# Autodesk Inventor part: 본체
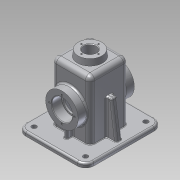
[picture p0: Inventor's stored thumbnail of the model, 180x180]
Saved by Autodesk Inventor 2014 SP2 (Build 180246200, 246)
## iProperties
Created: 2016-08
Part Number: 본체
Material: 알루미늄 6061
Document SubType Name: Modeling
Designer: user
Density: 2.71 g/cm^3
Appearance: 알루미늄 - 평지
Mass: 799.652 g
Surface Area: 913.3 cm^2
Volume: 295.075 cm^3
Author: user
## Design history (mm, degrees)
sketch "스케치2"
  geometry: L1 (52.5, -60)-(-52.5, -60); L2 (-52.5, -60)-(-52.5, 60); L3 (-52.5, 60)-(52.5, 60); L4 (52.5, 60)-(52.5, -60); L5 (52.5, -60)-(-52.5, 60); L6 (-52.5, -60)-(52.5, 60); 1 further point
  constraints: 12 end point, 2 midpoint, 2 parallel, 1 horizontal, 1 perpendicular
  dimensions: "d0" = 105 distance of L2.end L3.end; "d1" = 120 distance of L1.end L2.end
extrude "돌출1" new body sketch "스케치2" distance "d2" = 3; taper "d3" = 0 deg
sketch "스케치3"
  geometry: L1 (57.5, -65)-(-57.5, -65); L2 (-57.5, -65)-(-57.5, 65); L3 (-57.5, 65)-(57.5, 65); L4 (57.5, 65)-(57.5, -65); L5 (57.5, -65)-(-57.5, 65); L6 (-57.5, -65)-(57.5, 65); 1 further point
  constraints: 12 end point, 2 midpoint, 2 parallel, 1 horizontal, 1 perpendicular
  dimensions: "d4" = 115 distance of L2.end L3.end; "d5" = 130 distance of L1.end L2.end
extrude "돌출2" join sketch "스케치3" distance "d6" = 7; taper "d7" = 0 deg
sketch "스케치4"
  geometry: L1 (-32.5, -32.5)-(32.5, -32.5); L2 (32.5, -32.5)-(32.5, 32.5); L3 (32.5, 32.5)-(-32.5, 32.5); L4 (-32.5, 32.5)-(-32.5, -32.5); L5 (-32.5, -32.5)-(32.5, 32.5); L6 (32.5, -32.5)-(-32.5, 32.5); 1 further point
  constraints: 12 end point, 2 midpoint, 2 parallel, 1 horizontal, 1 perpendicular
  dimensions: "d8" = 65 distance of L3.end L2.end; "d9" = 65 distance of L2.end L1.end
extrude "돌출3" join sketch "스케치4" distance "d10" = 100; taper "d11" = 0 deg
sketch "스케치5"
  geometry: L1 (32.5, -32.5)-(-32.5, -32.5) reference; L2 (-32.5, -32.5)-(-32.5, 32.5) reference; L3 (-32.5, 32.5)-(32.5, 32.5) reference; L4 (32.5, 32.5)-(32.5, -32.5) reference; L5 (27.5, 27.5)-(-27.5, 27.5); L6 (-27.5, 27.5)-(-27.5, -27.5); L7 (-27.5, -27.5)-(27.5, -27.5); L8 (27.5, -27.5)-(27.5, 27.5); 1 further point
  constraints: 8 end point, 3 other
  dimensions: "d12" = 5 distance between parallel lines of L3 L5
extrude "돌출4" cut sketch "스케치5" distance "d13" = 105; taper "d14" = 0 deg
sketch "스케치6"
  geometry: C1 r 27.5 at (32.5, 45); 1 further point
  constraints: 1 centre point, 1 vertical alignment
  dimensions: "d15" = 55 diameter of C1; "d16" = 55 distance of point (32.5, -10) C1.centre
extrude "돌출5" join sketch "스케치6" distance "d17" = 15; taper "d18" = 0 deg
fillet "모깎기1" dims "d19" = 8
fillet "모깎기2" dims "d20" = 8
fillet "모깎기3" dims "d21" = 3
sketch "스케치9"
  geometry: L1 (-57.5, -65)-(-57.5, 65) reference; L2 (-32.5, 24.5)-(-32.5, -24.5) reference; L3 (-49.5, 5)-(-49.5, -5); L4 (-49.5, -5)-(-32.5, -5); L5 (-49.5, 5)-(-32.5, 5); L6 (-32.5, 5)-(-32.5, -5); 2 further points
  constraints: 8 end point, 2 perpendicular, 2 point on line, 1 collinear, 1 horizontal alignment, 1 midpoint, 1 parallel
  dimensions: "d36" = 10 distance of L3.start L3.end; "d37" = 8 distance between parallel lines of L1 L3
extrude "돌출7" join sketch "스케치9" distance "d38" = 60; taper "d39" = 0 deg
feature "면 기울기1" dims angle "d40" = 8 deg
sketch "스케치10"
  geometry: L1 (24.5, -32.5)-(-24.5, -32.5) reference; L2 (-3, -42.5)-(3, -42.5); L3 (-24.5, -27.5)-(24.5, -27.5) reference; L4 (3, -42.5)-(3, -27.5); L5 (-3, -42.5)-(-3, -27.5); L6 (-3, -27.5)-(3, -27.5); 2 further points
  constraints: 8 end point, 2 perpendicular, 2 point on line, 1 collinear, 1 midpoint, 1 parallel, 1 vertical alignment
  dimensions: "d41" = 15 distance of L2.end L4.end; "d42" = 6 distance of L2.start L2.end
extrude "돌출8" join sketch "스케치10" stored distance "d43" = 70; taper "d44" = 0 deg
sketch "스케치11"
  geometry: L1 (32.5, -47)-(32.5, 45) reference; 2 further points
  constraints: 1 other
  dimensions: "d46" = 32.5 distance from line of L1 point (0, -39); "d189" = 94 distance of point (0, 55) point (0, -39)
hole "구멍1" diameter "d51" = 35; stored, may be unused: countersink angle "d55" = 90 deg, drill point angle "d57" = 0 deg; dims "d49" = 10, "d50" = 10, "d52" = 6, "d53" = 4, "d54" = 2, "d56" = 17
hole "구멍2" diameter "d60" = 35; stored, may be unused: countersink angle "d64" = 90 deg, drill point angle "d66" = 0 deg; dims "d58" = 10, "d59" = 10, "d61" = 6, "d62" = 4, "d63" = 2, "d65" = 17
hole "구멍3" diameter "d69" = 30; stored, may be unused: countersink angle "d73" = 90 deg, drill point angle "d75" = 0 deg; dims "d67" = 10, "d68" = 10, "d70" = 6, "d71" = 4, "d72" = 2, "d74" = 3
hole "구멍4" diameter "d78" = 30; stored, may be unused: countersink angle "d82" = 90 deg, drill point angle "d84" = 0 deg; dims "d76" = 10, "d77" = 10, "d79" = 6, "d80" = 4, "d81" = 2, "d83" = 3
fillet "모깎기4" dims "d85" = 14
fillet "모깎기5" dims "d86" = 9
hole "구멍5" diameter "d89" = 8; stored, may be unused: countersink angle "d93" = 90 deg, drill point angle "d95" = 0 deg; dims "d87" = 10, "d88" = 10, "d90" = 6, "d91" = 4, "d92" = 2, "d94" = 3
hole "구멍6" diameter "d98" = 8; stored, may be unused: countersink angle "d102" = 90 deg, drill point angle "d104" = 0 deg; dims "d96" = 10, "d97" = 10, "d99" = 6, "d100" = 4, "d101" = 2, "d103" = 3
hole "구멍7" diameter "d107" = 8; stored, may be unused: countersink angle "d111" = 90 deg, drill point angle "d113" = 0 deg; dims "d105" = 10, "d106" = 10, "d108" = 6, "d109" = 4, "d110" = 2, "d112" = 3
hole "구멍8" diameter "d116" = 8; stored, may be unused: countersink angle "d120" = 90 deg, drill point angle "d122" = 0 deg; dims "d114" = 10, "d115" = 10, "d117" = 6, "d118" = 4, "d119" = 2, "d121" = 3
fillet "모깎기6" dims "d123" = 3
fillet "모깎기7" dims "d124" = 3
fillet "모깎기8" dims "d125" = 1
chamfer "모따기1" distance "d135" = 1; stored, may be unused: second distance "d136" = 2, angle "d137" = 45 deg
sketch "스케치12" dims "d138" = 42
  geometry: 3 further points
  constraints: 3 vertical alignment, 2 other
  dimensions: "d139" = 55 distance of point (0, -55) point (0, 0)
hole "구멍10" sketch "스케치12" at (0, 21) diameter "d140" = 3.242; stored, may be unused: countersink angle "d144" = 90 deg, drill point angle "d146" = 118 deg; dims "d141" = 8, "d142" = 4, "d143" = 2, "d145" = 10
fillet "모깎기9" dims "d161" = 0.3
node "작업 평면1"
sketch "스케치14"
  geometry: C1 r 20 at (0, 0); 1 further point
  constraints: 1 centre point, 1 coincident
  dimensions: "d163" = 40 diameter of C1
extrude "돌출9" join sketch "스케치14" stored distance "d164" = 70; taper "d165" = 7 deg
hole "구멍12" diameter "d168" = 21; stored, may be unused: countersink angle "d172" = 90 deg, drill point angle "d174" = 0 deg; dims "d166" = 10, "d167" = 10, "d169" = 7, "d170" = 4, "d171" = 2, "d173" = 9
chamfer "모따기2" distance "d175" = 1; stored, may be unused: second distance "d176" = 2, angle "d177" = 45 deg
sketch "스케치15" dims "d178" = 29
  geometry: 3 further points
  constraints: 2 vertical alignment, 1 coincident, 2 other
hole "구멍13" sketch "스케치15" at (0, -14.5) diameter "d179" = 2.459; stored, may be unused: countersink angle "d183" = 90 deg, drill point angle "d185" = 118 deg; dims "d180" = 7, "d181" = 4, "d182" = 2, "d184" = 9
feature "엠보싱2" dims "d190" = 0.5, "d191" = 0
node "솔리드1"
mirror "대칭1"
mirror "대칭2"
mirror "대칭3"
pattern_circular "원형 패턴1" dims angle "d148" = 360 deg
mirror "대칭4"
pattern_circular "원형 패턴3" dims angle "d187" = 360 deg
node "투영된 루프1"
